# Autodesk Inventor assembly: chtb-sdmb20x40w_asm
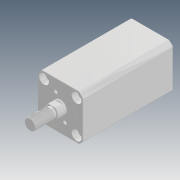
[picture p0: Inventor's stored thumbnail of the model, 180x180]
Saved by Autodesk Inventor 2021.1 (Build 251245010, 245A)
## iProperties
Company: Microsoft
Created: 2018-05
Part Number: chtb-sdmb20x40w_asm
Description: STEP AP214
Document SubType Name: Assembly
Designer: user
Title: chtb-sdmb20x40w_asm.STEP
Author: Windows
Revision Number: ÈÎºÎ
Sending System: SolidWorks 2015
Preprocessor: SwSTEP 2.0
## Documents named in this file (4)
- D:\Vault_2016\Projekty\Clamptek\Hydraulic\CHTB\CHTB-20\Inventor\CHTB-SDMB20x40W\chtb-sdmb20x40w_asm.iam
- D:\Vault_2016\Projekty\Clamptek\Hydraulic\CHTB\CHTB-20\Inventor\CHTB-SDMB20x40W\CHTB-SDMB20X40NBT.ipt
- D:\Vault_2016\Projekty\Clamptek\Hydraulic\CHTB\CHTB-20\Inventor\CHTB-SDMB20x40W\CHTB-SDMB20X40WHSG.ipt
- D:\Vault_2016\Projekty\Clamptek\Hydraulic\CHTB\CHTB-20\Inventor\CHTB-SDMB20x40W\QG_3.ipt
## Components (3 placed, 3 different names)
1. CHTB-SDMB20X40NBT_1
2. CHTB-SDMB20X40WHSG_2
3. QG_3_3
